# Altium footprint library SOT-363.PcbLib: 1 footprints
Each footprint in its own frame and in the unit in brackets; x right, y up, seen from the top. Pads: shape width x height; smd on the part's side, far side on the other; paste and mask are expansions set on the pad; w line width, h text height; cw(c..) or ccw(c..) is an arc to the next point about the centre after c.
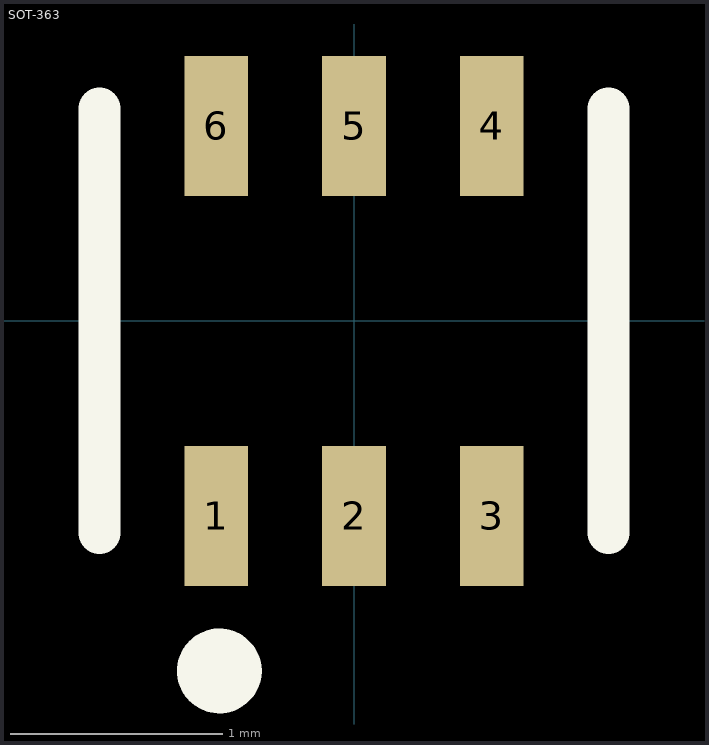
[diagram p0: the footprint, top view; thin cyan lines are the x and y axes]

## SOT-363 [mm]
pads (6):
  rect 0.3x0.66 smd mask+0.05: 1(-0.65,-0.92) 2(0,-0.92) 3(0.65,-0.92) 4(0.65,0.92) 5(0,0.92) 6(-0.65,0.92)
Top Overlay:
  circle w0.2: c-0.635,-1.651 r0.1
  lines w0.2: -1.2,-1 -1.2,1 ; 1.2,-1 1.2,1
3D body "User Library-SOT363-2.step": height 1.1, standoff 0, extent -1.1,-1.2 1.1,1.2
